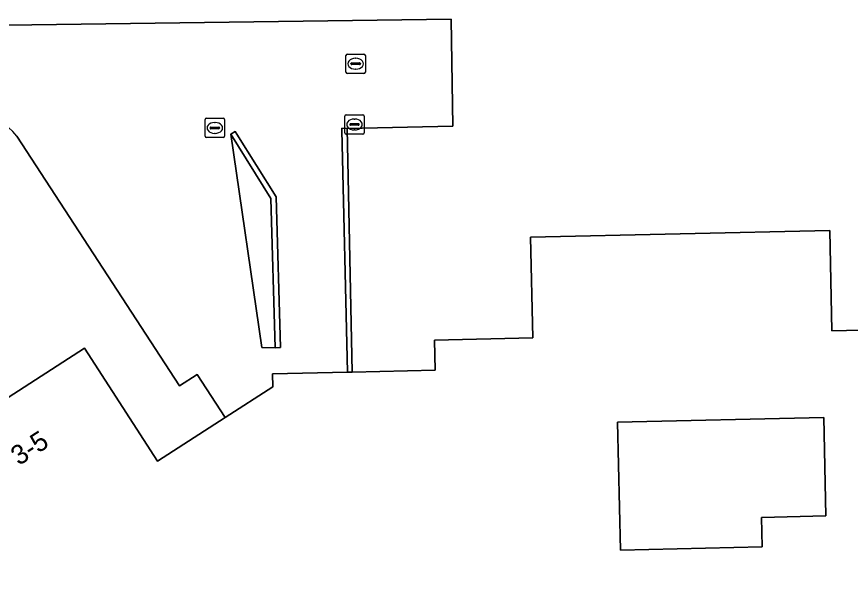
# Model space of a CAD drawing. Extents: x 162788 to 163838, y 385791 to 386523.
# Drawn here: x 163217.83 to 163260.81, y 386465.95 to 386494.75 of the extents above; entities that cross this region are included whole.
import ezdxf

# ---------------------------------------------------------------- set-up
doc = ezdxf.new("R2010")
doc.units = 0
for name, color, linetype in [('IMGEO_Erf', 7, 'Continuous'), ('IMGEO_Grasland_overig', 7, 'Continuous'), ('IMGEO_Kolk', 7, 'Continuous'), ('IMGEO_Muur', 7, 'Continuous'), ('IMGEO_Pand', 7, 'Continuous'), ('IMGEO_Pand_nummerreeks', 7, 'Continuous'), ('IMGEO_Rioolput', 7, 'Continuous'), ('IMGEO_Voetpad_open', 7, 'Continuous')]:
    doc.layers.add(name, color=color, linetype=linetype)

msp = doc.modelspace()

# ---------------------------------------------------------------- linework, layer by layer
at = {"layer": 'IMGEO_Erf'}
for points in [[(163267.522, 386495.587), (163240.009, 386495.549), (163216.052, 386495.316), (163216.052, 386494.295), (163240.232, 386494.621), (163240.311, 386489.109), (163234.862, 386488.99), (163235.127, 386476.428), (163239.403, 386476.524), (163239.368, 386478.072), (163244.437, 386478.187), (163244.32, 386483.376), (163259.751, 386483.725), (163259.868, 386478.556), (163261.371, 386478.59)], [(163211.892, 386465.954), (163215.708, 386468.416), (163213.144, 386472.391), (163221.319, 386477.666), (163225.084, 386471.832), (163228.579, 386474.087), (163227.128, 386476.307), (163226.228, 386475.729), (163217.828, 386488.592)]]:
    msp.add_lwpolyline(points, dxfattribs=at)
msp.add_lwpolyline([(163248.815, 386473.848), (163248.964, 386467.249), (163256.261, 386467.414), (163256.227, 386468.936), (163259.558, 386469.012), (163259.444, 386474.088)], close=True, dxfattribs=at)
msp.add_arc((163213.66, 386485.179), 5.387, 39.3166, 142.7964, dxfattribs=at)
at = {"layer": 'IMGEO_Grasland_overig'}
msp.add_lwpolyline([(163228.876, 386488.684), (163230.474, 386477.698), (163231.156, 386477.673), (163230.932, 386485.385)], close=True, dxfattribs=at)
at = {"layer": 'IMGEO_Kolk'}
for p, q in [((163227.62, 386489.514), (163228.472, 386489.514)), ((163234.746, 386488.767), (163234.746, 386489.619)), ((163234.821, 386489.693), (163235.673, 386489.693)), ((163235.747, 386489.619), (163235.747, 386488.767)), ((163227.545, 386488.588), (163227.545, 386489.44)), ((163227.847, 386489.057), (163228.245, 386489.057)), ((163228.033, 386489.294), (163228.058, 386489.294)), ((163228.546, 386489.44), (163228.546, 386488.588)), ((163235.005, 386489.187), (163235.005, 386489.199)), ((163235.443, 386489.15), (163235.045, 386489.15)), ((163235.048, 386489.236), (163235.446, 386489.236)), ((163235.234, 386489.473), (163235.259, 386489.473)), ((163235.489, 386489.199), (163235.489, 386489.187)), ((163227.804, 386489.008), (163227.804, 386489.02)), ((163228.242, 386488.971), (163227.844, 386488.971)), ((163228.056, 386488.734), (163228.031, 386488.734)), ((163228.288, 386489.02), (163228.288, 386489.008)), ((163235.673, 386488.693), (163234.821, 386488.693)), ((163235.257, 386488.913), (163235.232, 386488.913)), ((163228.472, 386488.514), (163227.62, 386488.514))]:
    msp.add_line(p, q, dxfattribs=at)
for points in [[(163227.62, 386489.514), (163228.472, 386489.514)], [(163234.746, 386488.767), (163234.746, 386489.619)], [(163234.821, 386489.693), (163235.673, 386489.693)], [(163235.747, 386489.619), (163235.747, 386488.767)], [(163227.545, 386488.588), (163227.545, 386489.44)], [(163228.546, 386489.44), (163228.546, 386488.588)], [(163235.673, 386488.693), (163234.821, 386488.693)], [(163228.472, 386488.514), (163227.62, 386488.514)]]:
    msp.add_lwpolyline(points, dxfattribs=at)
for centre, radius, start, end in [((163227.622, 386489.438), 0.0765, 91.552, 178.448), ((163227.622, 386489.438), 0.0765, 91.552, 178.448), ((163228.47, 386489.438), 0.0765, 1.552, 88.448), ((163228.47, 386489.438), 0.0765, 1.552, 88.448), ((163234.823, 386489.617), 0.0765, 91.552, 178.448), ((163234.823, 386489.617), 0.0765, 91.552, 178.448), ((163235.671, 386489.617), 0.0765, 1.552, 88.448), ((163235.671, 386489.617), 0.0765, 1.552, 88.448), ((163227.844, 386489.017), 0.0403, 85.8775, 175.7526), ((163228.249, 386489.019), 0.0386, 1.7309, 96.639), ((163235.045, 386489.196), 0.0403, 85.8775, 175.7526), ((163235.042, 386489.186), 0.0366, 178.938, 274.7102), ((163235.446, 386489.193), 0.043, 264.8664, 352.4533), ((163235.45, 386489.198), 0.0386, 1.7309, 96.639), ((163227.841, 386489.007), 0.0366, 178.938, 274.7102), ((163228.245, 386489.014), 0.043, 264.8664, 352.4533), ((163234.823, 386488.769), 0.0765, 181.552, 268.448), ((163234.823, 386488.769), 0.0765, 181.552, 268.448), ((163235.671, 386488.769), 0.0765, 271.552, 358.448), ((163235.671, 386488.769), 0.0765, 271.552, 358.448), ((163227.622, 386488.59), 0.0765, 181.552, 268.448), ((163227.622, 386488.59), 0.0765, 181.552, 268.448), ((163228.47, 386488.59), 0.0765, 271.552, 358.448), ((163228.47, 386488.59), 0.0765, 271.552, 358.448)]:
    msp.add_arc(centre, radius, start, end, dxfattribs=at)
for centre, major_axis, ratio, start_param, end_param in [((163228.032, 386489.014), (-0.387, 0.002), 0.722429, 4.712389, 7.853982), ((163228.057, 386489.014), (-0.39, 0.002), 0.717154, 1.570796, 4.712389), ((163235.233, 386489.193), (-0.387, 0.002), 0.722429, 4.712389, 7.853982), ((163235.258, 386489.193), (-0.39, 0.002), 0.717154, 1.570796, 4.712389)]:
    msp.add_ellipse(centre, major_axis=major_axis, ratio=ratio, start_param=start_param, end_param=end_param, dxfattribs=at)
at = {"layer": 'IMGEO_Muur'}
for points in [[(163231.426, 386477.696), (163231.215, 386485.47), (163229.186, 386488.701), (163229.102, 386488.834), (163228.876, 386488.684), (163230.932, 386485.385), (163231.156, 386477.673)], [(163234.862, 386488.99), (163234.593, 386489.009), (163234.595, 386488.899), (163234.878, 386476.422), (163235.127, 386476.428)]]:
    msp.add_lwpolyline(points, close=True, dxfattribs=at)
at = {"layer": 'IMGEO_Pand'}
msp.add_lwpolyline([(163261.371, 386478.59), (163259.868, 386478.556), (163259.751, 386483.725), (163244.32, 386483.376), (163244.437, 386478.187), (163239.368, 386478.072), (163239.403, 386476.524), (163235.127, 386476.428), (163234.878, 386476.422), (163231.024, 386476.335), (163231.038, 386475.673), (163228.579, 386474.087), (163225.084, 386471.832), (163221.319, 386477.666), (163213.144, 386472.391)], dxfattribs=at)
msp.add_lwpolyline([(163248.815, 386473.848), (163259.444, 386474.088), (163259.558, 386469.012), (163256.227, 386468.936), (163256.261, 386467.414), (163248.964, 386467.249)], close=True, dxfattribs=at)
at = {"layer": 'IMGEO_Rioolput'}
for p, q in [((163234.806, 386491.896), (163234.806, 386492.748)), ((163234.881, 386492.822), (163235.733, 386492.822)), ((163235.294, 386492.602), (163235.319, 386492.602)), ((163235.807, 386492.748), (163235.807, 386491.896)), ((163235.065, 386492.316), (163235.065, 386492.328)), ((163235.503, 386492.279), (163235.105, 386492.279)), ((163235.108, 386492.365), (163235.506, 386492.365)), ((163235.549, 386492.328), (163235.549, 386492.316)), ((163235.733, 386491.822), (163234.881, 386491.822)), ((163235.317, 386492.042), (163235.292, 386492.042))]:
    msp.add_line(p, q, dxfattribs=at)
for points in [[(163234.806, 386491.896), (163234.806, 386492.748)], [(163234.881, 386492.822), (163235.733, 386492.822)], [(163235.807, 386492.748), (163235.807, 386491.896)], [(163235.733, 386491.822), (163234.881, 386491.822)]]:
    msp.add_lwpolyline(points, dxfattribs=at)
for centre, radius, start, end in [((163234.883, 386492.746), 0.0765, 91.552, 178.448), ((163234.883, 386492.746), 0.0765, 91.552, 178.448), ((163235.731, 386492.746), 0.0765, 1.552, 88.448), ((163235.731, 386492.746), 0.0765, 1.552, 88.448), ((163235.105, 386492.325), 0.0403, 85.8775, 175.7526), ((163235.102, 386492.315), 0.0366, 178.938, 274.7102), ((163235.506, 386492.322), 0.043, 264.8664, 352.4533), ((163235.51, 386492.327), 0.0386, 1.7309, 96.639), ((163234.883, 386491.898), 0.0765, 181.552, 268.448), ((163234.883, 386491.898), 0.0765, 181.552, 268.448), ((163235.731, 386491.898), 0.0765, 271.552, 358.448), ((163235.731, 386491.898), 0.0765, 271.552, 358.448)]:
    msp.add_arc(centre, radius, start, end, dxfattribs=at)
for centre, major_axis, ratio, start_param, end_param in [((163235.293, 386492.322), (-0.387, 0.002), 0.722429, 4.712389, 7.853982), ((163235.318, 386492.322), (-0.39, 0.002), 0.717154, 1.570796, 4.712389)]:
    msp.add_ellipse(centre, major_axis=major_axis, ratio=ratio, start_param=start_param, end_param=end_param, dxfattribs=at)
at = {"layer": 'IMGEO_Voetpad_open'}
for points in [[(163234.595, 386488.899), (163234.593, 386489.009), (163234.862, 386488.99), (163240.311, 386489.109), (163240.232, 386494.621), (163216.052, 386494.295), (163212.563, 386494.248)], [(163217.828, 386488.592), (163226.228, 386475.729), (163227.128, 386476.307), (163228.579, 386474.087), (163231.038, 386475.673), (163231.024, 386476.335), (163234.878, 386476.422), (163234.595, 386488.899)]]:
    msp.add_lwpolyline(points, dxfattribs=at)
msp.add_lwpolyline([(163228.876, 386488.684), (163229.102, 386488.834), (163229.186, 386488.701), (163231.215, 386485.47), (163231.426, 386477.696), (163231.156, 386477.673), (163230.474, 386477.698)], close=True, dxfattribs=at)
msp.add_arc((163213.66, 386485.179), 5.387, 39.3166, 142.7964, dxfattribs=at)

# ---------------------------------------------------------------- texts
at = {"layer": 'IMGEO_Pand_nummerreeks'}
msp.add_text('3-5', height=1, rotation=32.8305, dxfattribs=at).set_placement((163217.942, 386471.583))

doc.saveas('drawing.dxf')
